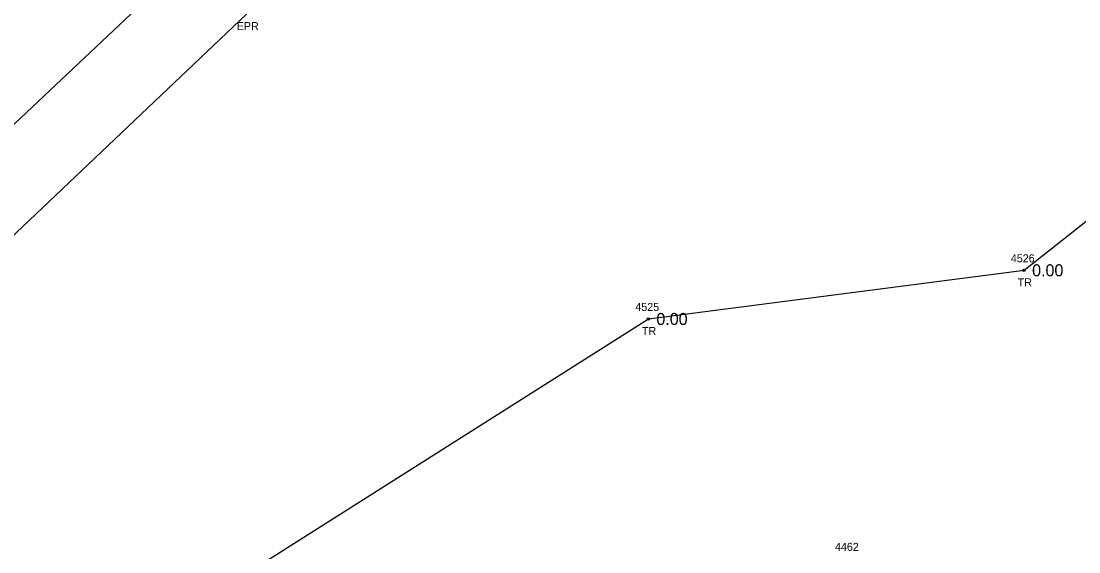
# Model space of a CAD drawing. Extents: x 1622501 to 1626664, y 1117816 to 1121579.
# Drawn here: x 1624963.5 to 1625095.7, y 1120119 to 1120185.2 of the extents above; entities that cross this region are included whole.
import ezdxf

# ---------------------------------------------------------------- set-up
doc = ezdxf.new("R2010")
doc.units = 0
for name, color, linetype in [('RD_EX_H2O_txCode', 7, 'Continuous'), ('RD_EX_Road', 7, 'Continuous'), ('RD_EX_Road_txCode', 7, 'Continuous'), ('RD_EX_TX_VEG_ELEV', 7, 'Continuous'), ('RD_EX_VEG', 7, 'Continuous'), ('RD_EX_VEG_txCode', 7, 'Continuous'), ('RD_HC_Cl', 7, 'Continuous'), ('RD_SMD_Locator', 7, 'Continuous')]:
    doc.layers.add(name, color=color, linetype=linetype)

msp = doc.modelspace()

# ---------------------------------------------------------------- linework, layer by layer
at = {"layer": 'RD_EX_Road'}
msp.add_lwpolyline([(1624481.69, 1119706.57), (1624518.07, 1119740.62), (1624554.52, 1119774.63), (1624590.99, 1119808.78), (1624627.13, 1119843.17), (1624664.12, 1119876.78), (1624700.28, 1119911.28), (1624736.97, 1119945.68), (1624773.63, 1119979.8), (1624810.11, 1120014.45), (1624846.42, 1120048.91), (1624882.77, 1120083.19), (1624919.14, 1120117.14), (1624955.41, 1120151.75), (1624991.66, 1120186.11), (1625027.75, 1120220.09), (1625065.42, 1120252.96), (1625104.19, 1120284.12), (1625143.2, 1120315.04), (1625181.69, 1120345.9), (1625220.31, 1120377.13)], dxfattribs=at)
at = {"layer": 'RD_EX_VEG'}
msp.add_lwpolyline([(1624512.21, 1119665.08), (1624623.15, 1119770.79), (1624648.99, 1119820.53), (1624692.77, 1119846.8), (1624723.16, 1119887.22), (1624826.69, 1119986.15), (1624990.88, 1120115.75), (1625041.88, 1120148.03), (1625088.84, 1120154.11), (1625168.57, 1120217.07), (1625166.16, 1120273.07), (1625241.55, 1120352.71), (1625279.72, 1120390.08), (1625351.21, 1120453.55), (1625384.83, 1120487.36), (1625414.17, 1120498.18), (1625443.21, 1120451.74)], dxfattribs=at)
at = {"layer": 'RD_HC_Cl'}
msp.add_line((1624870.49, 1120085.68), (1625124.67, 1120324.94), dxfattribs=at)
at = {"layer": 'RD_SMD_Locator'}
for centre in [(1625088.84, 1120154.11), (1625041.88, 1120148.03)]:
    msp.add_circle(centre, 0.15, dxfattribs=at)

# ---------------------------------------------------------------- texts
at = {"layer": 'RD_EX_H2O_txCode'}
msp.add_text('4462', height=1, dxfattribs=at).set_placement((1625065.2, 1120119.07))
at = {"layer": 'RD_EX_Road_txCode'}
msp.add_text('EPR', height=1, dxfattribs=at).set_placement((1624990.44, 1120184.11))
at = {"layer": 'RD_EX_TX_VEG_ELEV'}
for p in [(1625089.84, 1120153.36), (1625042.88, 1120147.28)]:
    msp.add_text('0.00', height=1.5, dxfattribs=at).set_placement(p)
at = {"layer": 'RD_EX_VEG_txCode'}
for s, p in [('4526', (1625087.18, 1120155.11)), ('TR', (1625088.04, 1120152.11)), ('4525', (1625040.25, 1120149.03)), ('TR', (1625041.08, 1120146.03))]:
    msp.add_text(s, height=1, dxfattribs=at).set_placement(p)

doc.saveas('drawing.dxf')
